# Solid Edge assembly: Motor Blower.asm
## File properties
Author: CADCIM
Template: ansi assembly.asm
Last saved by: CADCIM
Revision: 7
Application: Solid Edge
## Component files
cover.par
Lower Housing.par
upper housing.par
Blower.par
motorshaft.par
Motor.par
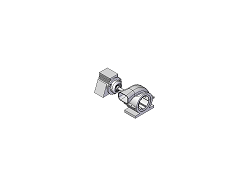
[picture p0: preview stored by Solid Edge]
